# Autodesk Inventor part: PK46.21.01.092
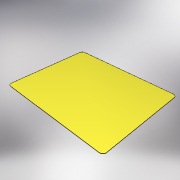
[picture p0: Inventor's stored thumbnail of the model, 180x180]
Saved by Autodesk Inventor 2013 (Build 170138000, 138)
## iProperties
Created: 2005-05
Part Number: PK46.21.01.092
Material: Steel, Mild
Document SubType Name: Modeling
Designer: PVitaliy
Manufacturer: Standard
Standards Organization: Custom
Density: 1 g/cm^3
Author: PVitaliy
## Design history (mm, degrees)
sketch "Эскиз2"
  geometry: L1 (0, 0)-(680, 0); L2 (680, 0)-(680, 540); L3 (680, 540)-(0, 540); L4 (0, 540)-(0, 0)
  constraints: 8 end point, 2 parallel, 1 horizontal, 1 perpendicular, 1 other
  dimensions: "d0" = 680 distance of L1.start L1.end; "d1" = 540 distance of L3.end L1.start
extrude "Выдавливание1" new body sketch "Эскиз2" distance "d2" = 2; taper "d3" = 0 deg
fillet "Сопряжение1" dims "d4" = 20
body "Solid1"
